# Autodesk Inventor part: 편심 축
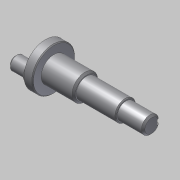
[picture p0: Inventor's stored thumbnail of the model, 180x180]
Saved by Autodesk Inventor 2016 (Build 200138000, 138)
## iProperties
Created: 2015-10
Part Number: 편심 축
Document SubType Name: Modeling
Designer: mdu
Density: 7.86 g/cm^3
Material: 강철, 연강
Mass: 78.4913 g
Surface Area: 37.9919 cm^2
Volume: 9.98617 cm^3
Appearance: Default
Author: mdu
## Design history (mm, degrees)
sketch "스케치1"
  geometry: L1 (1.75, -12.001)-(1.75, 11.999) reference; L2 (-16.95, -14)-(-16.95, 14) reference; L3 (-36.25, -18.06)-(-36.25, 18.06) reference; L4 (-41.25, 0)-(20.75, 0); L5 (-41.25, 0)-(-41.25, 12.5); L6 (-41.25, 12.5)-(-36.25, 12.5); L7 (-36.25, 12.5)-(-36.25, 7.5); L8 (-36.25, 7.5)-(-17.25, 7.5); L9 (-17.25, 6)-(5.75, 6); L10 (20.75, 5)-(20.75, 0); L11 (5.75, 6)-(5.75, 5); L12 (5.75, 5)-(20.75, 5); L13 (-17.25, -13.7)-(-17.25, 13.7) reference; L14 (-17.25, 7.5)-(-17.25, 6); 2 further points
  constraints: 20 end point, 7 perpendicular, 5 point on line, 1 collinear, 1 midpoint, 1 parallel
  dimensions: "d0" = 12 diameter of L9 L4; "d1" = 15 diameter of L8 L4; "d2" = 25 diameter of L6 L4; "d3" = 5 distance of L5.end L6.end; "d4" = 62 distance of L4.start L4.end; "d5" = 10 diameter of L12 L4; "d6" = 15 distance of L11.end L10.start
revolve "회전1" sketch "스케치1" stored, may be unused: angle "d7" = 90 deg
sketch "스케치2"
  geometry: C1 r 4 at (0, -7.5); C2 r 5 at (0, -7.5); C3 r 12.5 at (0, 0) reference; 1 further point
  constraints: 2 centre point, 1 coincident, 1 tangent, 1 vertical alignment
  dimensions: "d8" = 8 diameter of C1; "d9" = 7.5 distance of point (0, 0) C1.centre
extrude "돌출1" join sketch "스케치2" distance "d10" = 10; taper "d11" = 0 deg
extrude "돌출2" join sketch "스케치2" distance "d12" = 0.5; taper "d13" = 0 deg
node "작업 평면1"
sketch "스케치3"
  geometry: L1 (-7.5, 5)-(-7.5, -5) reference; L2 (-7.5, 1.5)-(3, 1.5); L3 (3, -1.5)-(-7.5, -1.5); A1 r 1.5 centre (3, 0) between (3, -1.5) and (3, 1.5); 2 further points
  constraints: 4 end point, 2 perpendicular, 2 point on circle, 2 point on line, 2 tangent, 1 centre point, 1 horizontal alignment, 1 midpoint
  dimensions: "d14" = 3 distance between parallel lines of L3 L2; "d15" = 12 dimension on A1 L1
extrude "돌출3" cut sketch "스케치3" distance "d16" = 1.8; taper "d17" = 0 deg
chamfer "모따기1" distance "d18" = 1; stored, may be unused: second distance "d19" = 2, angle "d20" = 45 deg
chamfer "모따기2" distance "d21" = 0.5; stored, may be unused: second distance "d22" = 2, angle "d23" = 45 deg
node "솔리드1"
node "참조1"
node "참조2"
node "참조3"
node "참조4"
